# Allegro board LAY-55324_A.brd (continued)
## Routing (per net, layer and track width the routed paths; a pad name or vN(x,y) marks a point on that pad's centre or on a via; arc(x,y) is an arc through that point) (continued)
N103091234: length 17
  TOP w0.102: U216.6 R284.1 v1(138.42,13.96)
  BOTTOM w0.102: R277.1 143.25,23.62 141.43,23.62 138.82,22.54 137.92,21.64 137.92,14.78 138.15,14.22 v1(138.42,13.96)
  BOTTOM w0.127: R284.1 v1(138.42,13.96)
N103097432: length 3.2
  BOTTOM w0.254: U217.16 59.69,34.03 C262.1
  BOTTOM w0.33: R376.2 R377.1 C262.1
N103098361: length 1.3
  BOTTOM w0.102: U217.14 58.04,32.12 R289.2
N103098539: length 1.4
  BOTTOM w0.102: R290.2 57.91,31.62 U217.13
N103098580: length 1.6
  BOTTOM w0.102: U217.12 58.04,31.12 R369.2
N103098723: length 1.9
  BOTTOM w0.102: R370.2 58.04,30.23 58.04,30.48 58.18,30.62 U217.11
N103098760: length 1.9
  BOTTOM w0.102: U217.3 61.71,32.12 61.85,32.26 61.85,32.51 R371.1
N103098763: length 1.6
  BOTTOM w0.102: U217.4 61.84,31.62 R372.1
N103098875: length 1.4
  BOTTOM w0.102: U217.5 61.88,31.12 R291.1
N103098937: length 1.3
  BOTTOM w0.102: U217.6 61.85,30.62 R292.1
N103099207: length 1.3
  BOTTOM w0.102: R373.1 59.44,29.21 59.69,29.47 U217.9
N103099681: length 6.1
  TOP w0.102: v1(61.21,33.27) v1(58.17,33.27)
  BOTTOM w0.102: U217.15 57.93,32.62 R374.1 57.71,33.27 v1(58.17,33.27) ; U217.2 61.21,32.67 v1(61.21,33.27)
N103100171: length 5.9
  TOP w0.102: v1(61.84,29.59) v1(58.72,29.59)
  BOTTOM w0.102: U217.10 v1(58.72,29.59) ; v1(61.84,29.59) R375.1 62.23,29.97 62.08,30.12 U217.7
N103106816: length 2
  BOTTOM w0.102: R384.2 TP216.1
N103106856: length 2.7
  BOTTOM w0.102: R386.2 TP218.1
N103106861: length 1.9
  BOTTOM w0.102: R385.2 TP217.1
N103107290: length 11.1
  TOP w0.102: U4.D12 143.95,31.97 143.61,32.32 143.61,34.88 143.43,35.05 143.43,36.2 143.59,36.35 143.59,37.26 143.05,37.8 143.05,39.81 v1(142.65,40.21)
  BOTTOM w0.102: v1(142.65,40.21) 142.98,39.88 R384.1
N103107293: length 9.4
  TOP w0.102: v1(141.4,38.99) 141.4,38.33 141.63,38.1 141.63,36.04 141.62,36.03 141.62,33 141.88,32.74 142.1,32.74 142.31,32.53 142.31,32.32 142.53,32.1 142.74,32.1 143.08,31.75 U4.C12
  BOTTOM w0.102: R385.1 v1(141.4,38.99)
N103107296: length 9.4
  TOP w0.102: v1(140.39,39.28) 140.39,38.49 141.27,37.6 141.27,33.03 141.58,32.72 141.58,32.4 141.92,32.06 142.13,32.06 142.43,31.75 U4.B12
  BOTTOM w0.102: v1(140.39,39.28) R386.1
N103163487: length 3.1
  TOP w0.381: J64.14 v1(28.83,47.08)
  BOTTOM w0.381: J64.14 v1(28.83,47.08) C36.1
N1029765922: length 1.2
  BOTTOM w0.102: U210.6 3.3,51.94 3.12,51.77 R234.1
N1029783922: length 1.8
  TOP w0.102: v1(3.94,5.33) 4.48,5.87 R233.1
  BOTTOM w0.102: v1(3.94,5.33) 3.56,4.95 3.56,4.87 U211.6

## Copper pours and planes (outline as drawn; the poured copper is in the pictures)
GND on BOTTOM (solid shape): 151.41,24.16 151.41,21.56 151.31,21.46 151.05,21.46 150.95,21.56 150.95,21.82 150.65,22.12 149.15,22.12 148.97,22.3 148.97,22.96 149.1,23.09 150.01,23.09 150.55,23.62 150.55,24.38 150.67,24.51 151.05,24.51
GND on TOP: 123.8,1.04 1.04,1.04 1.04,55.98 124.05,55.98 125.07,54.97 125.07,2.31 ; 8 cut-outs
GND on TOP: 8.25,29.59 8.25,15.01 1.65,15.01 1.65,28.78 3.43,28.78 3.78,29.13 3.78,29.59
GND on TOP: 165.13,1.04 128.73,1.04 128.73,55.98 165.13,55.98 ; 4 cut-outs
GND on BOTTOM: 66.04,11.43 66.04,11.94 66.67,12.57 67.82,12.57 67.94,12.45 67.94,10.03 67.82,9.91 67.56,9.91 67.44,9.78 67.44,8.89 67.18,8.89 67.18,9.78 67.06,9.91 66.67,9.91 66.42,10.16 66.42,11.05
GND on BOTTOM: 99.95,5.84 99.31,5.84 98.3,4.83 98.3,4.32 99.31,3.3 99.95,3.3 100.2,3.56 100.2,5.59
GND on BOTTOM: 62.1,14.1 64.64,14.1 64.9,13.84 65.28,13.84 65.53,14.1 65.53,15.11 64.9,15.75 62.36,15.75 61.98,15.37 61.98,14.22
GND on BOTTOM: 165.13,1.04 128.73,1.04 128.73,55.98 165.13,55.98 ; 9 cut-outs
GND on BOTTOM: 159.69,13.97 159.69,9.27 159.31,8.89 158.93,8.89 158.67,9.14 158.67,10.03 158.17,10.54 158.17,12.83 158.67,13.34 158.67,14.1 158.93,14.35 159.31,14.35
GND on BOTTOM: 1.04,55.98 124.05,55.98 125.07,54.97 125.07,2.31 123.8,1.04 1.04,1.04 1.04,4.01 1.9,4.01 1.9,8.28 1.04,8.28 ; 4 cut-outs
GND on L2_GND: 123.8,1.04 1.04,1.04 1.04,55.98 124.05,55.98 125.07,54.97 125.07,2.31
GND on L2_GND: 165.13,1.04 128.73,1.04 128.73,55.98 165.13,55.98
GND on L3_PWR: 1.04,29.51 1.04,14.35 8.89,14.35 8.89,28.7 8.08,29.51
VBUS_5V on TOP: 96.14,7.62 96.01,7.75 92.96,7.75 90.68,10.03 86.61,10.03 78.61,18.03 63.25,18.03 60.83,15.62 60.83,12.57 61.59,11.81 62.74,11.81 63.25,12.32 63.25,13.59 65.28,15.62 76.71,15.62 85.15,7.18 90.49,7.18 91.95,5.71 93.22,5.71 95.25,3.68 96.01,3.68 96.14,3.81
VBUS_5V on BOTTOM: 61.98,13.46 65.15,13.46 65.41,13.21 65.41,12.06 65.28,11.94 65.28,11.3 65.02,11.3 65.02,12.06 64.64,12.45 64.01,12.45 63.88,12.32 63.88,11.94 63.63,11.68 61.59,11.68 60.2,13.08 60.2,16.64 61.59,18.03 73.53,18.03 78.74,23.24 78.74,41.02 78.99,41.27 78.99,44.2 79.38,44.58 79.38,49.53 80.26,50.42 80.26,54.1 80.52,54.36 80.9,54.36 81.15,54.1 81.15,50.29 80.01,49.15 80.01,44.45 79.76,44.2 79.76,36.7 80.14,36.32 80.14,21.97 74.55,16.38 62.23,16.38 61.59,15.75 61.59,13.84
VBUS_5V on BOTTOM: 94.74,5.21 94.74,3.94 95,3.68 95.88,3.68 96.14,3.94 96.14,4.32 96.27,4.45 96.9,4.45 96.9,4.7 96.27,4.7 96.14,4.83 96.14,5.33 96.01,5.46 95,5.46
VBUS_5VDD on TOP: 160.17,46.68 160.17,46.25 160.83,45.59 160.83,26.54 159.31,25.02 159.31,24.26 159.69,23.88 161.59,23.88 162.36,24.64 162.36,45.81 161.33,46.83 160.33,46.83
VBUS_5VDD on TOP: 88.27,48.51 87.12,49.66 86.23,49.66 86.11,49.53 86.11,45.97 86.49,45.59 87.38,45.59 88.77,46.99 95.25,46.99 97.54,44.7 100.84,44.7 101.47,45.34 104.65,45.34 108.52,49.21 110.3,49.21 111.76,50.67 113.03,50.67 113.28,50.93 113.28,54.23 112.65,54.86 110.87,54.86 110.49,54.48 110.49,51.69 109.47,50.67 107.95,50.67 103.63,46.36 100.96,46.36 100.46,45.85 98.81,45.85 96.14,48.51
VDD_1V8 on TOP: 20.83,44.2 19.81,44.2 17.02,41.4 16.38,41.4 16.13,41.66 16.13,42.16 19.18,45.21 20.83,45.21 21.08,44.96 21.08,44.45
VDD_1V8 on TOP: 162.36,8.38 161.72,8.38 161.47,8.64 161.47,9.14 162.1,9.78 162.1,12.06 161.98,12.19 161.72,12.19 161.59,12.06 161.59,9.91 160.96,9.27 160.96,8.64 160.71,8.38 159.56,8.38 159.5,8.45 156.83,8.45 156.32,8.95 156.32,9.59 155.24,10.67 155.24,12.7 154.91,13.03 154.91,14 154.43,14.48 148.39,14.48 148.16,14.25 148.16,12.4 147.98,12.22 146.48,12.22 146.1,11.84 146.1,10.29 145.59,9.78 138.35,9.78 137.72,10.41 137.72,22.99 139.5,24.77 139.5,25.78 139.37,25.91 138.73,25.91 138.48,25.65 138.48,25.27 136.19,22.99 136.19,8.64 134.8,7.24 132.89,7.24 132,8.13 132,8.89 132.38,9.27 132.38,9.78 132.26,9.91 130.4,9.91 129.97,9.47 129.97,6.58 130.2,6.35 131.7,6.35 132.21,5.84 135.18,5.84 137.46,8.13 145.59,8.13 146.86,9.4 146.86,10.29 147.12,10.54 149.07,10.54 149.28,10.74 149.28,13.34 149.53,13.59 150.93,13.59 151.69,12.83 151.69,12.06 152.07,11.68 154.1,11.68 154.23,11.56 154.23,7.49 154.36,7.37 162.36,7.37 162.61,7.62 162.61,8.13
VDD_1V8 on BOTTOM: outline of 103 points within 19.05,13.59 78.61,51.18
VDD_1V8 on BOTTOM: 19.3,40.39 15.88,40.39 15.24,39.75 14.86,39.75 14.73,39.88 14.73,40.01 15.37,40.64 15.37,41.15 15.24,41.27 15.24,42.42 15.37,42.55 17.27,42.55 18.41,41.4 19.3,41.4 19.56,41.15 19.56,40.64
VDD_1V8 on BOTTOM: 156.01,10.54 154.48,10.54 154.23,10.79 154.23,11.56 154.1,11.68 152.07,11.68 151.82,11.94 151.82,12.45 151.94,12.57 152.83,12.57 153.34,13.08 153.85,13.08 154.86,12.06 154.86,11.81 155.12,11.56 156.26,11.56 156.39,11.43 156.39,10.92
VDD_1V8 on L3_PWR: 151.05,55.98 151.05,53.21 151.56,52.7 160.58,52.7 161.34,51.94 161.34,44.07 158.17,44.07 157.91,43.81 157.91,42.16 158.29,41.78 161.09,41.78 162.48,40.39 162.48,21.46 161.98,20.95 161.98,15.49 160.45,13.97 152.83,13.97 151.82,14.99 149.91,14.99 149.66,14.73 149.66,12.83 150.55,11.94 161.34,11.94 165.1,15.7 165.1,55.98
VDD_SOC_IN on TOP (solid shape): 151.05,20.83 151.05,19.56 150.29,18.8 149.28,18.8 148.51,19.56 148.51,19.81 148.64,19.94 148.64,21.21 150.67,21.21
VDD_SOC_IN on BOTTOM (solid shape): 151.05,20.62 151.05,19.56 150.29,18.8 149.28,18.8 148.51,19.56 148.51,20.45 148.64,20.57 149.28,20.57 149.73,21.03 150.65,21.03
VDD_SOC_IN on L3_PWR: 144.58,29.41 144.58,28.57 143.56,27.56 143.56,24.71 147.32,20.95 147.32,20.57 148.54,19.35 151.03,19.35 151.23,19.56 151.23,20.98 149.61,22.61 148.77,22.61 147.7,23.67 147.7,29.85 147.27,30.28 145.44,30.28
ANT_50E on TOP: 5.35,26.73 5.35,28.83 4.72,28.83 4.72,26.73
DCDC_3V3 on TOP: 157.78,9.52 157.78,10.67 157.66,10.79 156.64,10.79 156.39,10.54 156.39,9.52 156.51,9.4 157.66,9.4
DCDC_3V3 on BOTTOM: 68.45,14.99 68.45,13.08 68.58,12.95 68.58,10.03 68.45,9.91 68.45,8.89 68.58,8.76 69.47,8.76 69.6,8.89 69.6,14.86 69.34,15.11 68.58,15.11
DCDC_3V3 on BOTTOM: 157.91,9.02 157.91,10.29 157.78,10.41 157.78,10.79 157.53,11.05 156.9,11.05 156.39,10.54 156.39,9.52 157.15,8.76 157.66,8.76
DCDC_3V3 on L3_PWR: 165.1,1.04 128.73,1.04 128.73,55.98 150.8,55.98 150.8,53.09 151.43,52.45 160.48,52.45 161.09,51.84 161.09,41.4 162.2,40.28 162.2,21.54 161.7,21.03 161.7,15.52 160.4,14.22 152.93,14.22 151.92,15.24 149.83,15.24 149.4,14.81 149.4,12.78 150.47,11.71 161.47,11.71 165.1,15.34
DCDC_3V3 on L3_PWR: 123.8,1.04 1.04,1.04 1.04,55.98 124.1,55.98 125.07,55.02 125.07,2.31
DCDC_SW on BOTTOM: 65.53,12.19 65.53,12.45 66.17,13.08 66.17,15.11 66.29,15.24 67.44,15.24 67.56,15.11 67.56,13.08 67.44,12.95 66.55,12.95 65.79,12.19
NVCC_SEMC_1V8_3V3 on BOTTOM: 140.39,26.8 140.39,25.65 140.64,25.4 141.27,25.4 141.4,25.53 142.42,25.53 142.93,26.04 144.96,26.04 145.08,26.16 145.08,27.56 144.96,27.69 144.83,27.69 144.2,27.05 144.07,27.05 144.07,26.67 143.94,26.54 141.53,26.54 141.15,26.92 140.51,26.92
SHIELD on BOTTOM: 104.27,49.28 104.27,52.45 103.63,53.09 97.16,53.09 96.65,52.58 96.65,49.15 96.27,48.77 95,48.77 94.61,49.15 94.61,55.24 106.04,55.24 106.04,49.4 105.54,48.9 104.65,48.9
WL_3V3 on TOP: 25.65,33.53 29.21,33.53 30.48,32.26 42.93,32.26 43.31,32.64 43.31,33.27 43.56,33.53 44.45,33.53 44.7,33.27 44.7,32.13 43.94,31.37 26.29,31.37 25.4,32.26 25.4,33.27
WL_3V3 on BOTTOM: 36.07,32.26 36.07,19.68 36.7,19.05 36.96,19.05 37.85,19.94 37.85,32.26
N99781670 on TOP (solid shape): 149.48,25.25 149.48,24.28 149.86,23.9 150.52,23.9 150.67,23.75 150.67,21.97 148.64,21.97 148.64,23.57 149.17,24.1 149.17,24.49 149.1,24.56 149.1,24.71 149.17,24.79 149.17,25.07 149.1,25.15 149.1,25.3 149.43,25.3
N102954723 on TOP: 157.66,12.32 157.02,12.32 156.77,12.57 155.37,12.57 155.12,12.83 155.12,13.72 155.37,13.97 155.37,14.48 155.5,14.61 157.35,14.61 157.78,14.17 157.78,12.45
N102954723 on BOTTOM: 157.66,12.19 157.66,13.08 157.91,13.34 157.91,13.97 157.66,14.22 155.75,14.22 154.86,13.34 154.86,12.95 155.12,12.7 156.51,12.7 157.15,12.06 157.53,12.06

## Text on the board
BOTTOM: 170-55324 REV A | 07 | L04_SS
Board Geometry/Soldermask Bottom: 08 | SECONDARY SOLDERMASK
Ref Des/Silkscreen Bottom: -M | 09 | SECONDARY SILKSCREEN | -E
User.Comments: 1 OF 1 | TEST PROBE | 1/1 | 1 | 2
TOP: 04 | L1_PS
Board Geometry/Soldermask Top: 01 | PRIMARY SOLDERMASK
Ref Des/Silkscreen Top: 02 | PRIMARY SILKSCREEN | EXT | X-SLN-SVUI-IOT | MAIN
L2_GND: 05 | L2_GND
L3_PWR: 06 | L3_PWR
XSECTION_CHART: LAYERS | L1_PS | L4_SS | TRACE WIDTH | 4.00 | SE | IMPEDANCE | 50.00 | N/A | COPLANAR | TRACE SPACING | 6.00 | 90.00 | DIFF | REFERENCE LAYER | 2 | 3 | *  SURFACE - AIR 0 MIL | *  DIELECTRIC - SOLDERMASK 0.787 MIL | L1 TOP CONDUCTOR - COPPER 1.378 MIL | *  DIELECTRIC - VT-47 1080 2.746 MIL | L2 L2_GND PLANE - COPPER 1.378 MIL | *  DIELECTRIC - VT-47 CORE 47.244 MIL | L3 L3_PWR PLANE - COPPER 1.378 MIL | L4 BOTTOM CONDUCTOR - COPPER 1.378 MIL | DESIGN CROSS SECTION CHART | ___________________________ | TOTAL THICKNESS 59.822 MIL | 1-4 | SCALE: NONE | BOARD THICKNESS TOLERANCE +/-10% | IMAGECURESMARTXV501T, TAMURA DSR-2200TT19G AND PETERS ELPEMER 2467 ON BOTH SIDES OF THE BOARD | 2.540-6.350 MICRON (100-250 MICROINCH) OF NICKEL. | TO BE ONE OF -TAYO PSR-4000MPHF, PSR-2000 CE823HF, SUNCHEMICAL IMAGECURE XV501T, | .05080-.232 MICRON (2-8 MICROINCH) OF GOLD OVER | 22. | 19 | 16 | DETAIL | IMPEDANCE REQUIREMENTS | IMPEDANCE TOLERANCE IS 10% | LAYER STACKUP | COUNTERBORE/COUNTERSINK: TOP | B | A
DIMENSION: PRIMARY DATUM | GRID ORIGIN
BODY_CENTER: 03 | PRIMARY PASTEMASK
DISPLAY_TOP: 10 | SECONDARY PASTEMASK
User.11: OF 10
User.14: 22. THIS FAB_VIAFILL.ART SHOWS LOCATIONS OF VIA-IN-PAD TO BE FILLED. | 1/1 | 2
User.15: 24. | 1/1 | 3 | CAD DESIGNER: DELETE THIS FAB PAGE IF BACKDRILL IS NOT USED ON THIS DESIGN. | FAB SUPPLIER: DISREGARD THIS PAGE IF BACKDRILL REQUIRMENT IS NOT PROVIDED.
User.16: ORIGINAL RELEASE
User.20: TOP TO LAYER X | BACK DRILL REFERENCE | BOTTOM TO LAYER X | LAYER X | MUST CUT LAYER | LAYER X+1 | MUST NOT CUT LAYER | LAYER X-1
User.21: FIGURE | FINISHED_SIZE | 8.0 | 8.1 | 28.0 | 40.0 | 165.0 | 15.0 | 25.0 | 35.0 | 43.0 | 63.0 | 125.0 | 144.0 | 63.0x24.0 | 83.0x24.0 | DRILL CHART: TOP to BOTTOM | ALL UNITS ARE IN MILS | TOLERANCE_DRILL | +0.0/-8.0 | +0.0/-8.1 | +2.0/-2.0 | +3.0/-3.0 | +4.0/-4.0 | PLATED | NON-PLATED | QTY | 1254 | 17 | 14 | 4 | 1 | 7 | 6 | 2 | 8
User.22: Countersink | Angle | DSB | d1 | Drill | Size | TOP | BOTTOM
User.23: Countersink | 35 MIL | 90.00 | 15 MIL | Angle | DSB | d1 | Drill | Size | TOP | BOTTOM
User.24: FIGURE | DIAMETER | 35.0 | TOLERANCE | +2.0/-2.0 | COUNTERBORE/COUNTERSINK: TOP | ALL UNITS ARE IN MILS | ANGLE | 90.000 | DEPTH | - | QTY | 7
